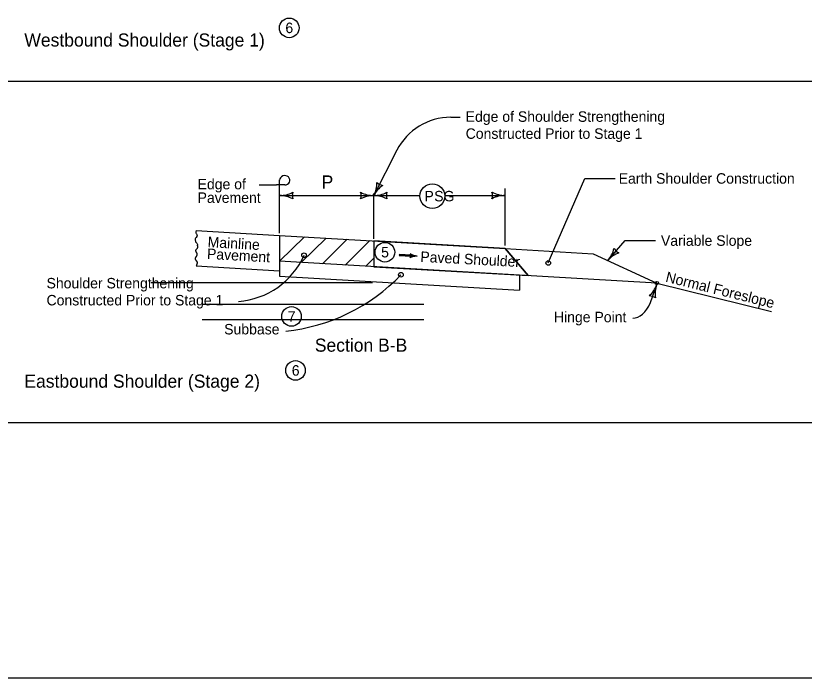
# Model space of a CAD drawing. Extents: x 10133 to 81668, y 5848 to 11018.
# Drawn here: x 11006 to 12210, y 7924 to 8936 of the extents above; entities that cross this region are included whole.
import ezdxf

# ---------------------------------------------------------------- set-up
doc = ezdxf.new("R2010")
doc.units = 0
for name, color, linetype in [('dsnStdLabel', 7, 'Continuous'), ('dsnStdLineWork', 7, 'Continuous'), ('dsnStdNote', 7, 'Continuous'), ('dsnStdShading', 7, 'Continuous'), ('PlanSheetShape', 7, 'Continuous'), ('SheetBorder', 7, 'Continuous'), ('SheetText', 7, 'Continuous'), ('ShtPlotShapeBatchPrint', 7, 'Continuous')]:
    doc.layers.add(name, color=color, linetype=linetype)

msp = doc.modelspace()

# ---------------------------------------------------------------- linework, layer by layer
at = {"layer": 'dsnStdLabel'}
for centre in [(11423.3, 8917.3), (11569.5, 8574.7), (11426.8, 8476.5), (11432.9, 8394.1)]:
    msp.add_circle(centre, 15, dxfattribs=at)
at = {"layer": 'dsnStdLineWork'}
for p, q in [((11281.2, 8607.8), (11408.7, 8600.4)), ((11408.7, 8600.4), (11408.7, 8546.4)), ((11408.7, 8600.4), (11753, 8580.4)), ((11552.4, 8592.1), (11552.4, 8552.2)), ((11752.5, 8580.6), (11752.5, 8580.6)), ((11753, 8580.5), (11887.7, 8572.1)), ((11753, 8580.4), (11788, 8539)), ((11887.7, 8572.1), (11984.8, 8527.6)), ((11281.2, 8553.8), (11408.7, 8546.4)), ((11984.8, 8527.6), (11408.7, 8560.8)), ((11775.2, 8554.1), (11775.2, 8554.1)), ((11408.7, 8546.4), (11408.7, 8538)), ((11408.7, 8538), (11775.2, 8516.9)), ((11775.2, 8539.7), (11775.2, 8516.9)), ((11212, 8528.5), (11550.5, 8528.5)), ((11984.8, 8527.6), (12159.8, 8484.3)), ((11290.6, 8495.5), (11629.1, 8495.5)), ((11290.6, 8471.8), (11629.1, 8471.8))]:
    msp.add_line(p, q, dxfattribs=at)
msp.add_ellipse((11984.8, 8527.6), major_axis=(2.58, 0), ratio=0.913811, dxfattribs=at)
for points in [[(11281.2, 8607.8), (11280.7, 8604.2), (11281.8, 8602.7), (11282.6, 8600.4), (11282, 8598.4), (11280.1, 8596), (11279.6, 8594.1), (11280.1, 8591.8), (11281, 8589.4), (11282, 8588.7), (11283.4, 8586.2), (11283.4, 8585.3)], [(11281.4, 8568.2), (11281.6, 8568.5), (11281.8, 8568.7), (11282.2, 8569.3), (11282.5, 8569.9), (11282.6, 8570.2), (11282.7, 8570.5), (11282.8, 8571.1), (11282.9, 8571.7), (11282.8, 8572.3), (11282.8, 8572.6), (11282.7, 8572.7), (11282.7, 8572.9), (11282.5, 8573.2), (11282.2, 8573.6), (11281.9, 8574), (11281.6, 8574.4), (11281.5, 8574.7), (11281.4, 8574.9), (11281.1, 8575.5), (11280.9, 8576.1), (11280.8, 8576.4), (11280.8, 8576.7), (11280.8, 8576.8), (11280.8, 8576.9), (11280.9, 8577.7), (11281.1, 8578.2), (11281.4, 8578.7), (11281.8, 8579.4), (11282.3, 8579.9), (11282.9, 8580.5), (11283.1, 8580.8), (11283.3, 8581.1), (11283.5, 8581.6), (11283.6, 8582.1), (11283.8, 8582.5), (11283.8, 8582.8), (11283.8, 8582.9), (11283.8, 8583), (11283.8, 8583.5), (11283.6, 8584), (11283.6, 8584.2), (11283.5, 8584.3), (11283.5, 8584.4), (11283.4, 8584.5), (11283.4, 8585.3)], [(11281.4, 8568.2), (11281.2, 8568), (11281, 8567.8), (11280.7, 8567.5), (11280.5, 8567.2), (11280.4, 8567), (11280.3, 8566.7), (11280, 8566.1), (11279.9, 8565.8), (11279.8, 8565.5), (11279.7, 8565.2), (11279.7, 8565.1), (11279.7, 8564.9), (11279.7, 8564.4), (11279.8, 8563.9), (11280, 8563.4), (11280.3, 8562.9), (11280.7, 8562.2), (11281.3, 8561.7), (11281.8, 8561.2), (11282, 8560.8), (11282.2, 8560.5), (11282.6, 8559.6), (11282.7, 8559.1), (11282.7, 8558.6), (11282.7, 8558.3), (11282.6, 8558), (11282.6, 8557.7), (11282.5, 8557.5), (11282.2, 8556.3), (11282, 8555.7), (11281.8, 8555.1), (11281.6, 8554.5), (11281.5, 8554.2), (11281.3, 8553.9), (11281.2, 8553.8)]]:
    msp.add_spline(points, degree=3, dxfattribs=at)
at = {"layer": 'dsnStdNote'}
for centre in [(11446, 8570), (11446, 8570), (11818.9, 8558.2), (11818.9, 8558.2), (11593.9, 8540.2), (11593.9, 8540.2)]:
    msp.add_circle(centre, 3.54, dxfattribs=at)
at = {"layer": 'dsnStdShading'}
msp.add_line((12307.8, 8835.4), (10152.2, 8835.4), dxfattribs=at)
at = {"layer": 'PlanSheetShape'}
for p, q in [((11552.5, 8592.1), (11552.4, 8552.2)), ((11753, 8580.5), (11552.5, 8592.1)), ((11788, 8539), (11753, 8580.5)), ((11552.4, 8552.2), (11788, 8539))]:
    msp.add_line(p, q, dxfattribs=at)
at = {"layer": 'SheetBorder'}
msp.add_lwpolyline([(10132.5, 9944), (13267.5, 9944), (13267.5, 7924), (10132.5, 7924)], close=True, dxfattribs=at)
at = {"layer": 'SheetText'}
for p, q in [((11670.1, 8780.7), (11684.4, 8780.7)), ((11587.8, 8730.3), (11552.4, 8661.2)), ((11408.7, 8664.5), (11408.7, 8685.3)), ((11818.9, 8558.2), (11874.6, 8687.3)), ((11874.6, 8687.3), (11921, 8687.3)), ((11377.3, 8677.3), (11404, 8677.3)), ((11416.5, 8677.3), (11404, 8677.3)), ((11753, 8585), (11753, 8671.7)), ((11408.7, 8603.6), (11408.7, 8664.5)), ((11408.7, 8661.2), (11623, 8661.2)), ((11552.4, 8594.9), (11552.4, 8664.5)), ((11660.8, 8661.3), (11753, 8661.3)), ((11408.7, 8560.8), (11446.5, 8598.2)), ((11441.7, 8558.9), (11479.5, 8596.3)), ((11474, 8557.1), (11511.8, 8594.5)), ((11508.6, 8555.1), (11546.4, 8592.5)), ((11909.9, 8561.9), (11936.5, 8592.4)), ((11936.5, 8592.4), (11982.9, 8592.4)), ((11540.2, 8553.2), (11552.4, 8565.4)), ((11609.7, 8569.3), (11591.5, 8570.4)), ((11609.6, 8568.4), (11609.6, 8568.4)), ((11609.7, 8570.3), (11609.7, 8570.3)), ((11975, 8497.7), (11984.5, 8525.3))]:
    msp.add_line(p, q, dxfattribs=at)
for points in [[(11609.7, 8570.3), (11591.6, 8571.3), (11591.4, 8569.4), (11609.6, 8568.4), (11609.7, 8570), (11591.8, 8571.1), (11591.7, 8569.6), (11609.2, 8568.6), (11609.3, 8569.8), (11592, 8570.8), (11592, 8569.8), (11609, 8568.8), (11609.1, 8569.5), (11592.2, 8570.6), (11592.2, 8570), (11608.8, 8569.1)], [(11609.3, 8571.5), (11610, 8570.3), (11610, 8568.7), (11609.2, 8567.3), (11612, 8568.2), (11615.2, 8568.8), (11616.1, 8568.9), (11613.8, 8569.5), (11610.6, 8570.7), (11609.7, 8571.3), (11609.8, 8567.7), (11614.7, 8569), (11610.1, 8570.5), (11610.1, 8568.1), (11613.5, 8569.1), (11610.5, 8569.9), (11610.3, 8568.5), (11612.4, 8569), (11610.9, 8569.5), (11610.7, 8568.9), (11611.5, 8569)]]:
    msp.add_lwpolyline(points, dxfattribs=at)
msp.add_circle((11641.9, 8660.3), 18.9, dxfattribs=at)
for centre, radius, start, end in [((11670.1, 8688.3), 92.4, 90, 152.9341), ((11514.6, 8680.5), 42.5, 332.9341, 1.0066), ((11590.3, 8641.8), 42.5, 124.8616, 152.9341), ((11568.7, 8692.9), 16.4, 225.2008, 260.6675), ((11408.7, 8703.7), 42.5, 270, 298.0725), ((11408.7, 8618.7), 42.5, 61.9275, 90), ((11444.3, 8661.2), 16.4, 162.2666, 197.7334), ((11516.8, 8661.2), 16.4, 342.2666, 17.7334), ((11552.4, 8703.7), 42.5, 241.9275, 270), ((11552.4, 8618.7), 42.5, 90, 118.0725), ((11552.4, 8703.7), 42.5, 270, 298.0725), ((11552.4, 8618.7), 42.5, 61.9275, 90), ((11588.1, 8661.2), 16.4, 162.2666, 197.7334), ((11717.3, 8661.3), 16.4, 342.2666, 17.7333), ((11753, 8703.8), 42.5, 241.9275, 270), ((11753, 8618.8), 42.5, 90, 118.0725), ((11877.9, 8589.9), 42.5, 318.8454, 346.9178), ((11941.9, 8534), 42.5, 110.7729, 138.8454), ((11933.4, 8588.8), 16.4, 211.112, 246.5787), ((11337.4, 8618.2), 118.9, 274.0851, 336.0699), ((11390, 8734.9), 282, 275.6784, 316.2844), ((11944.3, 8539.1), 42.5, 312.9788, 341.0513), ((12024.7, 8511.5), 42.5, 161.0513, 189.1238), ((11972.9, 8491.6), 16.4, 53.3179, 88.7846)]:
    msp.add_arc(centre, radius, start, end, dxfattribs=at)
for centre, major_axis, ratio, start_param, end_param in [((11416.5, 8684.5), (-7.81, 0), 0.913811, 1.570796, 6.283185), ((11605.9, 8569.5), (3.88, 0), 0.913811, 5.202895, 7.237436), ((11618.2, 8548.5), (22.2, 0), 0.913811, 1.537172, 2.061295), ((11621, 8588.9), (-22.2, 0), 0.913811, 0.954258, 1.478381), ((11947.9, 8535.5), (0, 61.5), 0.559383, 3.141593, 4.048985)]:
    msp.add_ellipse(centre, major_axis=major_axis, ratio=ratio, start_param=start_param, end_param=end_param, dxfattribs=at)
at = {"layer": 'ShtPlotShapeBatchPrint'}
msp.add_line((10152.2, 8314.4), (13247.9, 8314.4), dxfattribs=at)

# ---------------------------------------------------------------- texts
at = {"layer": 'dsnStdLabel'}
for s, p in [('6', (11417.5, 8909.3)), ('5', (11563.7, 8566.7)), ('7', (11421.1, 8468.5)), ('6', (11427.2, 8386.1))]:
    msp.add_text(s, height=16, dxfattribs=at).set_placement(p)
at = {"layer": 'SheetText'}
for s, height, p in [('Westbound Shoulder (Stage 1)', 20, (11018.8, 8888.7)), ('Edge of Shoulder Strengthening', 16, (11692.8, 8773.8)), ('Constructed Prior to Stage 1', 16, (11692.8, 8747.8)), ('Earth Shoulder Construction', 16, (11926.5, 8679.3)), ('Edge of ', 16, (11283.4, 8670.7)), ('P', 20, (11472.8, 8671.9)), ('Pavement', 16, (11283.4, 8650)), ('P', 16, (11629.8, 8652.3)), ('SG', 16, (11644.7, 8652.3)), ('Variable Slope', 16, (11991, 8584.4)), ('Shoulder Strengthening', 16, (11052.7, 8519.4)), ('Constructed Prior to Stage 1', 16, (11052.7, 8493.4)), ('Hinge Point', 16, (11827.6, 8467.7)), ('Subbase', 16, (11324, 8449.1)), ('Section B-B', 20, (11462.4, 8422.7)), ('Eastbound Shoulder (Stage 2)', 20, (11018.8, 8367.7))]:
    msp.add_text(s, height=height, dxfattribs=at).set_placement(p)
for s, rotation, p in [('Mainline', 356.7346, (11298.4, 8582.5)), ('Pavement', 356.7346, (11297.4, 8564.5)), ('Paved Shoulder ', 356.983, (11623.3, 8560)), ('Normal Foreslope', 346.0988, (11997, 8529.7))]:
    msp.add_text(s, height=16, rotation=rotation, dxfattribs=at).set_placement(p)

doc.saveas('drawing.dxf')
